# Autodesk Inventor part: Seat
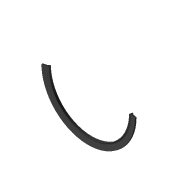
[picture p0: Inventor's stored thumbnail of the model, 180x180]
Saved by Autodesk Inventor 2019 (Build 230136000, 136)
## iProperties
Created: 2019-09
Part Number: Seat
Material: Generic
Document SubType Name: Modeling
Designer: Admin
Density: 1 g/cm^3
Appearance: Default
Author: Admin
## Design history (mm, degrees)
sketch "Sketch2" dims "d73" = 10
  geometry: L1 (0, -5.774)-(0, 34.644) reference; L2 (36.569, 0)-(-219.416, 0) reference; L3 (-111.955, 10.747)-(-182.847, 28.87); L4 (-124.137, 5.573)-(-119.271, 24.608); L5 (-131.133, 6.47)-(-126.395, 25.003); L6 (-129.425, 13.149)-(-129.239, 13.876); L7 (-130.879, 13.521)-(-130.693, 14.247); L8 (-132.332, 13.892)-(-132.146, 14.619); L9 (-133.785, 14.264)-(-133.599, 14.99); L10 (-135.238, 14.635)-(-135.053, 15.362); L11 (-136.692, 15.007)-(-136.506, 15.733); L12 (-138.145, 15.378)-(-137.959, 16.105); L13 (-139.598, 15.75)-(-139.412, 16.476); L14 (-127.607, 12.684)-(-129.425, 13.149); L15 (-129.239, 13.876)-(-130.693, 14.247); L16 (-130.879, 13.521)-(-132.332, 13.892); L17 (-132.146, 14.619)-(-133.599, 14.99); L18 (-133.785, 14.264)-(-135.238, 14.635); L19 (-135.053, 15.362)-(-136.506, 15.733); L20 (-137.959, 16.105)-(-139.412, 16.476); L21 (-136.692, 15.007)-(-138.145, 15.378); L22 (-139.598, 15.75)-(-140.891, 16.08); L23 (-140.891, 16.08)-(-140.395, 18.018); L24 (-123.263, 8.993)-(-122.148, 13.353); L25 (-120.159, 21.133)-(-125.025, 2.098); L26 (-121.033, 17.713)-(-122.148, 13.353); L27 (-126.616, 16.56)-(-128.435, 17.024); L28 (-128.435, 17.024)-(-128.62, 16.298); L29 (-128.62, 16.298)-(-130.074, 16.669); L30 (-129.888, 17.396)-(-130.074, 16.669); L31 (-129.888, 17.396)-(-131.341, 17.767); L32 (-131.341, 17.767)-(-131.527, 17.041); L33 (-131.527, 17.041)-(-132.98, 17.412); L34 (-132.794, 18.139)-(-132.98, 17.412); L35 (-132.794, 18.139)-(-134.248, 18.51); L36 (-134.248, 18.51)-(-134.433, 17.784); L37 (-134.433, 17.784)-(-135.887, 18.155); L38 (-135.701, 18.882)-(-135.887, 18.155); L39 (-135.701, 18.882)-(-137.154, 19.253); L40 (-137.154, 19.253)-(-137.34, 18.527); L41 (-137.34, 18.527)-(-138.793, 18.898); L42 (-138.607, 19.625)-(-138.793, 18.898); L43 (-138.607, 19.625)-(-139.9, 19.955); L44 (-139.9, 19.955)-(-140.395, 18.018); A1 r 4.5 centre (-122.148, 13.353) between (-126.27, 11.549) and (-123.263, 8.993); A2 r 2 centre (-128.103, 10.747) between (-126.27, 11.549) and (-127.607, 12.684); A3 r 4.5 centre (-122.148, 13.353) between (-121.033, 17.713) and (-124.899, 16.914); A4 r 2 centre (-126.121, 18.497) between (-126.616, 16.56) and (-124.899, 16.914); 3 further points
  constraints: 84 end point, 23 symmetric about line, 9 point on circle, 8 point on line, 6 tangent, 4 centre point, 2 perpendicular, 1 coincident, 1 collinear, 24 other
  dimensions: "d60" = 122.148 distance from line of L1 point (-122.148, 13.353); "d61" = 13.353 distance from line of L2 point (-122.148, 13.353); "d62" = 9 diameter of A1; "d63" = 14.34 deg angle of L2 L3; "d65" = 7 distance between parallel lines of L4 L5; "d66" = 2 radius of A2; "d67" = 0.75 distance of L6.start L6.end; "d70" = 1.5 distance of L6.start L7.start; "d76" = 1.25 distance between parallel lines of L3 L15; "d77" = 1.334 distance between parallel lines of L13 L23
revolve "Revolution2" sketch "Sketch2" stored, may be unused: angle "d79" = 90 deg
body "Solid2"
other parameters: "d11" = 4.5, "d12" = 2, "d13" = 2, "d64" = 2, "d75" = 0.75 (derived)
